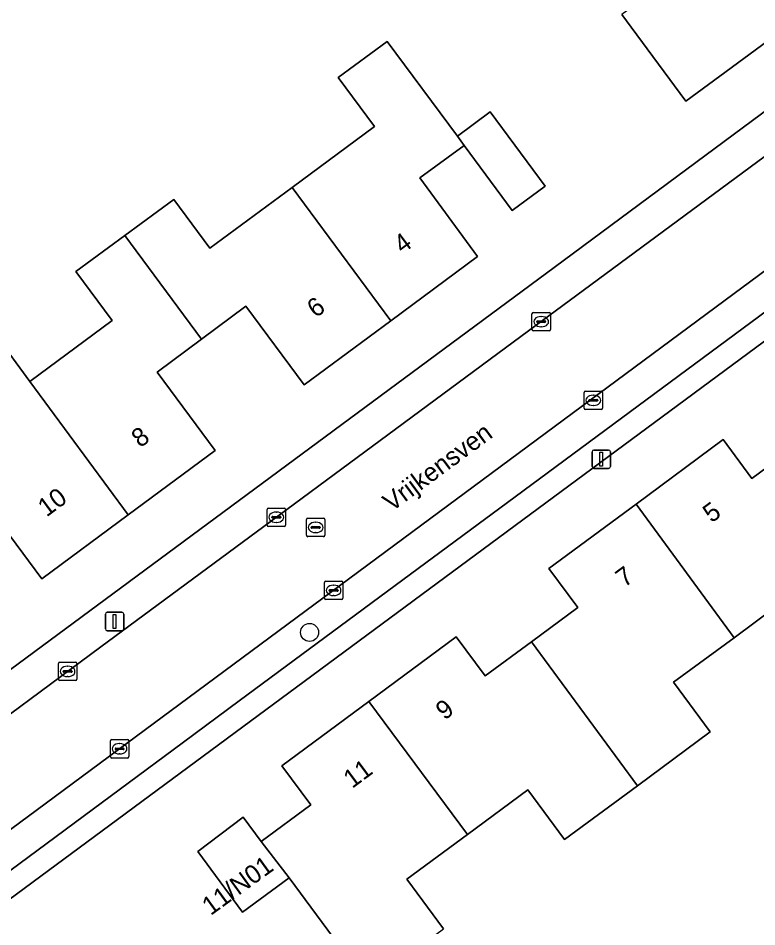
# Model space of a CAD drawing. Extents: x 163426 to 164192, y 380329 to 381641.
# Drawn here: x 163663.86 to 163703.91, y 381284.84 to 381334.12 of the extents above; entities that cross this region are included whole.
import ezdxf

# ---------------------------------------------------------------- set-up
doc = ezdxf.new("R2010")
doc.units = 0
for name, color, linetype in [('IMGEO_Boom', 7, 'Continuous'), ('IMGEO_Erf', 7, 'Continuous'), ('IMGEO_Kolk', 7, 'Continuous'), ('IMGEO_Lichtmast', 7, 'Continuous'), ('IMGEO_Muur', 7, 'Continuous'), ('IMGEO_Openbare_ruimte_label', 7, 'Continuous'), ('IMGEO_Pand', 7, 'Continuous'), ('IMGEO_Pand_nummerreeks', 7, 'Continuous'), ('IMGEO_Parkeervlak_open', 7, 'Continuous'), ('IMGEO_Rijbaan_lokaal_open', 7, 'Continuous'), ('IMGEO_Rioolput', 7, 'Continuous'), ('IMGEO_Voetpad_open', 7, 'Continuous')]:
    doc.layers.add(name, color=color, linetype=linetype)

msp = doc.modelspace()

# ---------------------------------------------------------------- linework, layer by layer
at = {"layer": 'IMGEO_Boom'}
msp.add_circle((163679.663, 381300.802), 0.489, dxfattribs=at)
at = {"layer": 'IMGEO_Erf'}
for points in [[(163706.775, 381334.547), (163701.911, 381330.966), (163700.07, 381329.61), (163697.097, 381333.631), (163696.592, 381334.313)], [(163703.68, 381328.564), (163710.193, 381333.382), (163711.148, 381334.089)], [(163662.649, 381316.914), (163664.494, 381314.412), (163668.96, 381317.718), (163666.996, 381320.372), (163669.637, 381322.327), (163672.294, 381324.293), (163674.258, 381321.639), (163678.719, 381324.94), (163683.185, 381328.246), (163681.221, 381330.9), (163683.87, 381332.86), (163687.675, 381327.715), (163689.453, 381329.034), (163692.44, 381325.01), (163690.65, 381323.68), (163688.039, 381327.219), (163685.639, 381325.46), (163688.77, 381321.19), (163684.065, 381317.709), (163679.365, 381314.232), (163676.215, 381318.491), (163673.804, 381316.708), (163671.394, 381314.925), (163674.544, 381310.666), (163669.828, 381307.177), (163665.136, 381303.706), (163661.986, 381307.964)], [(163649.769, 381288.678), (163692.92, 381320.603), (163703.68, 381328.564)], [(163740.553, 381295.871), (163741.259, 381296.424), (163738.778, 381299.792), (163718.602, 381327.167), (163657.027, 381281.631)], [(163681.524, 381283.478), (163678.553, 381287.5), (163676.033, 381285.637), (163673.601, 381288.929), (163676.067, 381290.775), (163677.04, 381289.465), (163679.722, 381291.458), (163678.154, 381293.566), (163682.884, 381297.066), (163687.613, 381300.566), (163689.174, 381298.444), (163691.691, 381300.297), (163694.204, 381302.148), (163692.642, 381304.268), (163697.365, 381307.765), (163702.09, 381311.262), (163703.643, 381309.153), (163706.14, 381310.993)], [(163705.959, 381302.944), (163702.677, 381300.519), (163699.401, 381298.099), (163701.388, 381295.41), (163697.436, 381292.49), (163693.488, 381289.573), (163691.502, 381292.263), (163688.221, 381289.839), (163684.943, 381287.417), (163686.931, 381284.727)]]:
    msp.add_lwpolyline(points, dxfattribs=at)
at = {"layer": 'IMGEO_Kolk'}
for p, q in [((163691.72, 381317.233), (163691.72, 381318.085)), ((163691.795, 381318.159), (163692.647, 381318.159)), ((163692.022, 381317.702), (163692.42, 381317.702)), ((163692.208, 381317.939), (163692.233, 381317.939)), ((163692.721, 381318.085), (163692.721, 381317.233)), ((163691.979, 381317.653), (163691.979, 381317.665)), ((163692.417, 381317.616), (163692.019, 381317.616)), ((163692.231, 381317.379), (163692.206, 381317.379)), ((163692.463, 381317.665), (163692.463, 381317.653)), ((163692.647, 381317.159), (163691.795, 381317.159)), ((163694.545, 381312.966), (163694.545, 381313.818)), ((163694.62, 381313.892), (163695.472, 381313.892)), ((163695.546, 381313.818), (163695.546, 381312.966)), ((163694.804, 381313.386), (163694.804, 381313.398)), ((163695.242, 381313.349), (163694.844, 381313.349)), ((163694.847, 381313.435), (163695.245, 381313.435)), ((163695.033, 381313.672), (163695.058, 381313.672)), ((163695.288, 381313.398), (163695.288, 381313.386)), ((163695.472, 381312.892), (163694.62, 381312.892)), ((163695.056, 381313.112), (163695.031, 381313.112)), ((163677.361, 381306.624), (163677.361, 381307.476)), ((163677.436, 381307.55), (163678.288, 381307.55)), ((163678.362, 381307.476), (163678.362, 381306.624)), ((163677.62, 381307.044), (163677.62, 381307.056)), ((163678.058, 381307.007), (163677.66, 381307.007)), ((163677.663, 381307.093), (163678.061, 381307.093)), ((163677.849, 381307.33), (163677.874, 381307.33)), ((163678.104, 381307.056), (163678.104, 381307.044)), ((163678.288, 381306.55), (163677.436, 381306.55)), ((163677.872, 381306.77), (163677.847, 381306.77)), ((163680.463, 381302.657), (163680.463, 381303.509)), ((163680.538, 381303.583), (163681.39, 381303.583)), ((163681.464, 381303.509), (163681.464, 381302.657)), ((163680.722, 381303.077), (163680.722, 381303.089)), ((163681.16, 381303.04), (163680.762, 381303.04)), ((163680.765, 381303.126), (163681.163, 381303.126)), ((163680.951, 381303.363), (163680.976, 381303.363)), ((163681.206, 381303.089), (163681.206, 381303.077)), ((163681.39, 381302.583), (163680.538, 381302.583)), ((163680.974, 381302.803), (163680.949, 381302.803)), ((163666.04, 381298.262), (163666.04, 381299.114)), ((163666.115, 381299.188), (163666.967, 381299.188)), ((163667.041, 381299.114), (163667.041, 381298.262)), ((163666.299, 381298.682), (163666.299, 381298.694)), ((163666.737, 381298.645), (163666.339, 381298.645)), ((163666.342, 381298.731), (163666.74, 381298.731)), ((163666.528, 381298.968), (163666.553, 381298.968)), ((163666.783, 381298.694), (163666.783, 381298.682)), ((163666.967, 381298.188), (163666.115, 381298.188)), ((163666.551, 381298.408), (163666.526, 381298.408)), ((163668.859, 381294.066), (163668.859, 381294.918)), ((163668.934, 381294.992), (163669.786, 381294.992)), ((163669.347, 381294.772), (163669.372, 381294.772)), ((163669.86, 381294.918), (163669.86, 381294.066)), ((163669.118, 381294.486), (163669.118, 381294.498)), ((163669.556, 381294.449), (163669.158, 381294.449)), ((163669.161, 381294.535), (163669.559, 381294.535)), ((163669.37, 381294.212), (163669.345, 381294.212)), ((163669.602, 381294.498), (163669.602, 381294.486)), ((163669.786, 381293.992), (163668.934, 381293.992))]:
    msp.add_line(p, q, dxfattribs=at)
for points in [[(163691.72, 381317.233), (163691.72, 381318.085)], [(163691.795, 381318.159), (163692.647, 381318.159)], [(163692.721, 381318.085), (163692.721, 381317.233)], [(163692.647, 381317.159), (163691.795, 381317.159)], [(163694.545, 381312.966), (163694.545, 381313.818)], [(163694.62, 381313.892), (163695.472, 381313.892)], [(163695.546, 381313.818), (163695.546, 381312.966)], [(163695.472, 381312.892), (163694.62, 381312.892)], [(163677.361, 381306.624), (163677.361, 381307.476)], [(163677.436, 381307.55), (163678.288, 381307.55)], [(163678.362, 381307.476), (163678.362, 381306.624)], [(163678.288, 381306.55), (163677.436, 381306.55)], [(163680.463, 381302.657), (163680.463, 381303.509)], [(163680.538, 381303.583), (163681.39, 381303.583)], [(163681.464, 381303.509), (163681.464, 381302.657)], [(163681.39, 381302.583), (163680.538, 381302.583)], [(163666.04, 381298.262), (163666.04, 381299.114)], [(163666.115, 381299.188), (163666.967, 381299.188)], [(163667.041, 381299.114), (163667.041, 381298.262)], [(163666.967, 381298.188), (163666.115, 381298.188)], [(163668.859, 381294.066), (163668.859, 381294.918)], [(163668.934, 381294.992), (163669.786, 381294.992)], [(163669.86, 381294.918), (163669.86, 381294.066)], [(163669.786, 381293.992), (163668.934, 381293.992)]]:
    msp.add_lwpolyline(points, dxfattribs=at)
for centre, radius, start, end in [((163691.797, 381318.083), 0.0765, 91.552, 178.448), ((163691.797, 381318.083), 0.0765, 91.552, 178.448), ((163692.019, 381317.662), 0.0403, 85.8775, 175.7526), ((163692.424, 381317.664), 0.0386, 1.7309, 96.639), ((163692.645, 381318.083), 0.0765, 1.552, 88.448), ((163692.645, 381318.083), 0.0765, 1.552, 88.448), ((163691.797, 381317.235), 0.0765, 181.552, 268.448), ((163691.797, 381317.235), 0.0765, 181.552, 268.448), ((163692.016, 381317.652), 0.0366, 178.938, 274.7102), ((163692.42, 381317.659), 0.043, 264.8664, 352.4533), ((163692.645, 381317.235), 0.0765, 271.552, 358.448), ((163692.645, 381317.235), 0.0765, 271.552, 358.448), ((163694.622, 381313.816), 0.0765, 91.552, 178.448), ((163694.622, 381313.816), 0.0765, 91.552, 178.448), ((163695.47, 381313.816), 0.0765, 1.552, 88.448), ((163695.47, 381313.816), 0.0765, 1.552, 88.448), ((163694.844, 381313.395), 0.0403, 85.8775, 175.7526), ((163694.841, 381313.385), 0.0366, 178.938, 274.7102), ((163695.245, 381313.392), 0.043, 264.8664, 352.4533), ((163695.249, 381313.397), 0.0386, 1.7309, 96.639), ((163694.622, 381312.968), 0.0765, 181.552, 268.448), ((163694.622, 381312.968), 0.0765, 181.552, 268.448), ((163695.47, 381312.968), 0.0765, 271.552, 358.448), ((163695.47, 381312.968), 0.0765, 271.552, 358.448), ((163677.438, 381307.474), 0.0765, 91.552, 178.448), ((163677.438, 381307.474), 0.0765, 91.552, 178.448), ((163678.286, 381307.474), 0.0765, 1.552, 88.448), ((163678.286, 381307.474), 0.0765, 1.552, 88.448), ((163677.66, 381307.053), 0.0403, 85.8775, 175.7526), ((163677.657, 381307.043), 0.0366, 178.938, 274.7102), ((163678.061, 381307.05), 0.043, 264.8664, 352.4533), ((163678.065, 381307.055), 0.0386, 1.7309, 96.639), ((163677.438, 381306.626), 0.0765, 181.552, 268.448), ((163677.438, 381306.626), 0.0765, 181.552, 268.448), ((163678.286, 381306.626), 0.0765, 271.552, 358.448), ((163678.286, 381306.626), 0.0765, 271.552, 358.448), ((163680.54, 381303.507), 0.0765, 91.552, 178.448), ((163680.54, 381303.507), 0.0765, 91.552, 178.448), ((163681.388, 381303.507), 0.0765, 1.552, 88.448), ((163681.388, 381303.507), 0.0765, 1.552, 88.448), ((163680.762, 381303.086), 0.0403, 85.8775, 175.7526), ((163680.759, 381303.076), 0.0366, 178.938, 274.7102), ((163681.163, 381303.083), 0.043, 264.8664, 352.4533), ((163681.167, 381303.088), 0.0386, 1.7309, 96.639), ((163680.54, 381302.659), 0.0765, 181.552, 268.448), ((163680.54, 381302.659), 0.0765, 181.552, 268.448), ((163681.388, 381302.659), 0.0765, 271.552, 358.448), ((163681.388, 381302.659), 0.0765, 271.552, 358.448), ((163666.117, 381299.112), 0.0765, 91.552, 178.448), ((163666.117, 381299.112), 0.0765, 91.552, 178.448), ((163666.965, 381299.112), 0.0765, 1.552, 88.448), ((163666.965, 381299.112), 0.0765, 1.552, 88.448), ((163666.339, 381298.691), 0.0403, 85.8775, 175.7526), ((163666.336, 381298.681), 0.0366, 178.938, 274.7102), ((163666.74, 381298.688), 0.043, 264.8664, 352.4533), ((163666.744, 381298.693), 0.0386, 1.7309, 96.639), ((163666.117, 381298.264), 0.0765, 181.552, 268.448), ((163666.117, 381298.264), 0.0765, 181.552, 268.448), ((163666.965, 381298.264), 0.0765, 271.552, 358.448), ((163666.965, 381298.264), 0.0765, 271.552, 358.448), ((163668.936, 381294.916), 0.0765, 91.552, 178.448), ((163668.936, 381294.916), 0.0765, 91.552, 178.448), ((163669.784, 381294.916), 0.0765, 1.552, 88.448), ((163669.784, 381294.916), 0.0765, 1.552, 88.448), ((163668.936, 381294.068), 0.0765, 181.552, 268.448), ((163668.936, 381294.068), 0.0765, 181.552, 268.448), ((163669.158, 381294.495), 0.0403, 85.8775, 175.7526), ((163669.155, 381294.485), 0.0366, 178.938, 274.7102), ((163669.559, 381294.492), 0.043, 264.8664, 352.4533), ((163669.563, 381294.497), 0.0386, 1.7309, 96.639), ((163669.784, 381294.068), 0.0765, 271.552, 358.448), ((163669.784, 381294.068), 0.0765, 271.552, 358.448)]:
    msp.add_arc(centre, radius, start, end, dxfattribs=at)
for centre, major_axis, ratio, start_param, end_param in [((163692.207, 381317.659), (-0.387, 0.002), 0.722429, 4.712389, 7.853982), ((163692.232, 381317.659), (-0.39, 0.002), 0.717154, 1.570796, 4.712389), ((163695.032, 381313.392), (-0.387, 0.002), 0.722429, 4.712389, 7.853982), ((163695.057, 381313.392), (-0.39, 0.002), 0.717154, 1.570796, 4.712389), ((163677.848, 381307.05), (-0.387, 0.002), 0.722429, 4.712389, 7.853982), ((163677.873, 381307.05), (-0.39, 0.002), 0.717154, 1.570796, 4.712389), ((163680.95, 381303.083), (-0.387, 0.002), 0.722429, 4.712389, 7.853982), ((163680.975, 381303.083), (-0.39, 0.002), 0.717154, 1.570796, 4.712389), ((163666.527, 381298.688), (-0.387, 0.002), 0.722429, 4.712389, 7.853982), ((163666.552, 381298.688), (-0.39, 0.002), 0.717154, 1.570796, 4.712389), ((163669.346, 381294.492), (-0.387, 0.002), 0.722429, 4.712389, 7.853982), ((163669.371, 381294.492), (-0.39, 0.002), 0.717154, 1.570796, 4.712389)]:
    msp.add_ellipse(centre, major_axis=major_axis, ratio=ratio, start_param=start_param, end_param=end_param, dxfattribs=at)
at = {"layer": 'IMGEO_Lichtmast'}
for p, q in [((163694.981, 381309.798), (163694.981, 381310.598)), ((163694.981, 381310.598), (163694.981, 381309.798)), ((163695.081, 381310.698), (163695.871, 381310.698)), ((163695.871, 381310.698), (163695.081, 381310.698)), ((163695.971, 381310.598), (163695.971, 381309.798)), ((163695.971, 381309.798), (163695.971, 381310.598)), ((163695.871, 381309.698), (163695.081, 381309.698)), ((163695.081, 381309.698), (163695.871, 381309.698)), ((163668.592, 381300.994), (163668.592, 381301.794)), ((163668.592, 381301.794), (163668.592, 381300.994)), ((163668.692, 381301.894), (163669.482, 381301.894)), ((163669.482, 381301.894), (163668.692, 381301.894)), ((163669.582, 381301.794), (163669.582, 381300.994)), ((163669.582, 381300.994), (163669.582, 381301.794)), ((163669.482, 381300.894), (163668.692, 381300.894)), ((163668.692, 381300.894), (163669.482, 381300.894))]:
    msp.add_line(p, q, dxfattribs=at)
for points in [[(163695.401, 381310.573), (163695.551, 381310.573), (163695.551, 381309.823), (163695.401, 381309.823), (163695.401, 381310.573)], [(163669.012, 381301.769), (163669.162, 381301.769), (163669.162, 381301.019), (163669.012, 381301.019), (163669.012, 381301.769)]]:
    msp.add_lwpolyline(points, dxfattribs=at)
for centre, start, end in [((163695.081, 381310.598), 90, 180), ((163695.081, 381310.598), 90, 180), ((163695.871, 381310.598), 0, 90), ((163695.871, 381310.598), 360, 90), ((163695.081, 381309.798), 180, 270), ((163695.081, 381309.798), 180, 270), ((163695.871, 381309.798), 270, 0), ((163695.871, 381309.798), 270, 0), ((163668.692, 381301.794), 90, 180), ((163668.692, 381301.794), 90, 180), ((163669.482, 381301.794), 0, 90), ((163669.482, 381301.794), 360, 90), ((163668.692, 381300.994), 180, 270), ((163668.692, 381300.994), 180, 270), ((163669.482, 381300.994), 270, 0), ((163669.482, 381300.994), 270, 0)]:
    msp.add_arc(centre, 0.1, start, end, dxfattribs=at)
at = {"layer": 'IMGEO_Muur'}
msp.add_lwpolyline([(163692.92, 381320.603), (163703.68, 381328.564)], dxfattribs=at)
at = {"layer": 'IMGEO_Pand'}
for points in [[(163696.592, 381334.313), (163697.097, 381333.631), (163700.07, 381329.61), (163701.911, 381330.966), (163706.775, 381334.547), (163708.53, 381335.84), (163706.83, 381338.13), (163705.619, 381337.238), (163703.839, 381339.652)], [(163684.065, 381317.709), (163688.77, 381321.19), (163685.639, 381325.46), (163688.039, 381327.219), (163687.675, 381327.715), (163683.87, 381332.86), (163681.221, 381330.9), (163683.185, 381328.246), (163678.719, 381324.94)], [(163688.039, 381327.219), (163690.65, 381323.68), (163692.44, 381325.01), (163689.453, 381329.034), (163687.675, 381327.715)], [(163684.065, 381317.709), (163678.719, 381324.94), (163674.258, 381321.639), (163672.294, 381324.293), (163669.637, 381322.327), (163673.804, 381316.708), (163676.215, 381318.491), (163679.365, 381314.232)], [(163664.494, 381314.412), (163669.828, 381307.177), (163674.544, 381310.666), (163671.394, 381314.925), (163673.804, 381316.708), (163669.637, 381322.327), (163666.996, 381320.372), (163668.96, 381317.718)], [(163664.494, 381314.412), (163662.649, 381316.914), (163658.184, 381313.609), (163658.069, 381313.765), (163655.428, 381311.81), (163659.576, 381306.181), (163661.986, 381307.964), (163665.136, 381303.706), (163669.828, 381307.177)], [(163702.677, 381300.519), (163705.959, 381302.944), (163707.946, 381300.254), (163711.9, 381303.176), (163706.14, 381310.993), (163703.643, 381309.153), (163702.09, 381311.262), (163697.365, 381307.765)], [(163702.677, 381300.519), (163697.365, 381307.765), (163692.642, 381304.268), (163694.204, 381302.148), (163691.691, 381300.297), (163697.436, 381292.49), (163701.388, 381295.41), (163699.401, 381298.099)], [(163697.436, 381292.49), (163691.691, 381300.297), (163689.174, 381298.444), (163687.613, 381300.566), (163682.884, 381297.066), (163688.221, 381289.839), (163691.502, 381292.263), (163693.488, 381289.573)], [(163678.553, 381287.5), (163681.524, 381283.478), (163682.836, 381281.703), (163686.931, 381284.727), (163684.943, 381287.417), (163688.221, 381289.839), (163682.884, 381297.066), (163678.154, 381293.566), (163679.722, 381291.458), (163677.04, 381289.465)], [(163678.553, 381287.5), (163677.04, 381289.465), (163676.067, 381290.775), (163673.601, 381288.929), (163676.033, 381285.637)]]:
    msp.add_lwpolyline(points, close=True, dxfattribs=at)
at = {"layer": 'IMGEO_Parkeervlak_open'}
for points in [[(163710.833, 381325.231), (163656.677, 381285.107)], [(163659.971, 381285.341), (163672.822, 381294.849), (163675.849, 381297.088), (163684.721, 381303.652), (163690.817, 381308.162), (163698.807, 381314.074), (163704.911, 381318.588), (163709.791, 381322.2)]]:
    msp.add_lwpolyline(points, dxfattribs=at)
at = {"layer": 'IMGEO_Rijbaan_lokaal_open'}
msp.add_lwpolyline([(163656.677, 381285.107), (163710.833, 381325.231), (163712.71, 381326.586), (163715.289, 381328.447), (163711.359, 381331.806), (163694.161, 381319.1), (163691.113, 381316.849), (163682.665, 381310.607), (163677.183, 381306.556), (163668.338, 381300.021), (163662.864, 381295.976), (163653.949, 381289.389), (163650.902, 381287.137), (163650.108, 381286.551)], dxfattribs=at)
at = {"layer": 'IMGEO_Rioolput'}
for p, q in [((163679.493, 381306.072), (163679.493, 381306.924)), ((163679.568, 381306.998), (163680.42, 381306.998)), ((163680.494, 381306.924), (163680.494, 381306.072)), ((163679.752, 381306.492), (163679.752, 381306.504)), ((163680.19, 381306.455), (163679.792, 381306.455)), ((163679.795, 381306.541), (163680.193, 381306.541)), ((163679.981, 381306.778), (163680.006, 381306.778)), ((163680.236, 381306.504), (163680.236, 381306.492)), ((163680.42, 381305.998), (163679.568, 381305.998)), ((163680.004, 381306.218), (163679.979, 381306.218))]:
    msp.add_line(p, q, dxfattribs=at)
for points in [[(163679.493, 381306.072), (163679.493, 381306.924)], [(163679.568, 381306.998), (163680.42, 381306.998)], [(163680.494, 381306.924), (163680.494, 381306.072)], [(163680.42, 381305.998), (163679.568, 381305.998)]]:
    msp.add_lwpolyline(points, dxfattribs=at)
for centre, radius, start, end in [((163679.57, 381306.922), 0.0765, 91.552, 178.448), ((163679.57, 381306.922), 0.0765, 91.552, 178.448), ((163680.418, 381306.922), 0.0765, 1.552, 88.448), ((163680.418, 381306.922), 0.0765, 1.552, 88.448), ((163679.792, 381306.501), 0.0403, 85.8775, 175.7526), ((163679.789, 381306.491), 0.0366, 178.938, 274.7102), ((163680.193, 381306.498), 0.043, 264.8664, 352.4533), ((163680.197, 381306.503), 0.0386, 1.7309, 96.639), ((163679.57, 381306.074), 0.0765, 181.552, 268.448), ((163679.57, 381306.074), 0.0765, 181.552, 268.448), ((163680.418, 381306.074), 0.0765, 271.552, 358.448), ((163680.418, 381306.074), 0.0765, 271.552, 358.448)]:
    msp.add_arc(centre, radius, start, end, dxfattribs=at)
for centre, major_axis, ratio, start_param, end_param in [((163679.98, 381306.498), (-0.387, 0.002), 0.722429, 4.712389, 7.853982), ((163680.005, 381306.498), (-0.39, 0.002), 0.717154, 1.570796, 4.712389)]:
    msp.add_ellipse(centre, major_axis=major_axis, ratio=ratio, start_param=start_param, end_param=end_param, dxfattribs=at)
at = {"layer": 'IMGEO_Voetpad_open'}
msp.add_lwpolyline([(163682.665, 381310.607), (163691.113, 381316.849), (163694.161, 381319.1), (163711.359, 381331.806), (163710.193, 381333.382), (163703.68, 381328.564), (163692.92, 381320.603), (163649.769, 381288.678), (163650.902, 381287.137), (163653.949, 381289.389), (163662.864, 381295.976), (163668.338, 381300.021), (163677.183, 381306.556)], close=True, dxfattribs=at)
for points in [[(163657.027, 381281.631), (163718.602, 381327.167)], [(163709.791, 381322.2), (163704.911, 381318.588), (163698.807, 381314.074), (163690.817, 381308.162), (163684.721, 381303.652), (163675.849, 381297.088), (163672.822, 381294.849), (163659.971, 381285.341)]]:
    msp.add_lwpolyline(points, dxfattribs=at)

# ---------------------------------------------------------------- texts
at = {"layer": 'IMGEO_Openbare_ruimte_label'}
msp.add_text('Vrijkensven', height=1, rotation=36.5374, dxfattribs=at).set_placement((163684.112, 381307.318))
at = {"layer": 'IMGEO_Pand_nummerreeks'}
for s, rotation, p in [('4', 36.4947, (163684.699, 381321.312)), ('6', 36.4947, (163679.996, 381317.833)), ('8', 36.4939, (163670.475, 381310.79)), ('10', 36.4917, (163665.4, 381307.035)), ('5', 36.5112, (163701.458, 381306.713)), ('7', 36.5112, (163696.734, 381303.216)), ('9', 36.5028, (163686.978, 381296.015)), ('11', 36.5028, (163681.97, 381292.31)), ('11/N01', 35.9229, (163674.296, 381285.418))]:
    msp.add_text(s, height=1, rotation=rotation, dxfattribs=at).set_placement(p)

doc.saveas('drawing.dxf')
